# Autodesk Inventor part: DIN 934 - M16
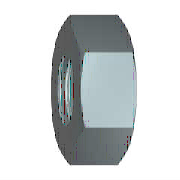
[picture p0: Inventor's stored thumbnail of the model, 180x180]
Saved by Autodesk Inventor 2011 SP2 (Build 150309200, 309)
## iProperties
Created: 2010-02
Part Number: DIN 934 - M16
Material: Stahl, weich, unlegiert
Description: Sechskantmutter
Document SubType Name: Modeling
Standard: DIN 934
Designer: JRE
Standards Organization: DIN
Language: de-DE
Size Designation: M16
Categories: <MemberInstance><Categories><Category DisplayName="Verbindungselemente" InternalName="e4da775c-781d-43d5-af7c-5136215cf5a6" Mnemonic="FSTN"><Category DisplayNam
Density: 1 g/cm^3
IsCustomPart: 0
Author: JRE
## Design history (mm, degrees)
body "Solid1"
workaxis "Work Axis1"
workplane "Work Plane1"
sketch "Skizze1"
  geometry: L1 (-13.856, 0)-(-6.928, 12); L2 (-6.928, 12)-(6.928, 12); L3 (6.928, 12)-(13.856, 0); L4 (13.856, 0)-(6.928, -12); L5 (6.928, -12)-(-6.928, -12); L6 (-6.928, -12)-(-13.856, 0); 2 further points
  constraints: 12 end point, 1 coincident, 1 horizontal, 11 other
  dimensions: "d0" = 27.71281 distance of L3.end L1.start (= 1.1547 x SW)
extrude "Körper" new body sketch "Skizze1" distance "d1" = 13 (= KOH); taper "d2" = 0 deg
revolve "Fase1" stored, may be unused: angle "d7" = 90 deg
sketch "Skizze3"
  geometry: 4 further points
  constraints: 1 coincident, 1 other
hole "Gewinde" sketch "Skizze3" diameter "d25" = 13.835; stored, may be unused: countersink angle "d29" = 82 deg, drill point angle "d31" = 118 deg; dims "d26" = 6, "d27" = 4, "d28" = 2, "d30" = 8
chamfer "Fase2" distance "d8" = 1.08253 (= -0.5 x GD1 + 0.5 x NND); stored, may be unused: angle "d9" = 30 deg, second distance "d40" = 1.08253 (= -0.5 x GD1 + 0.5 x NND)
chamfer "Fase3" distance "d10" = 1.08253 (= -0.5 x GD1 + 0.5 x NND); stored, may be unused: angle "d11" = 30 deg, second distance "d41" = 1.08253 (= -0.5 x GD1 + 0.5 x NND)
sketch "Skizze2"
  geometry: L1 (0, 6.928)-(0, 13.856) reference; L2 (0, 13.856)-(13, 13.856) reference; L3 (13, 6.928)-(13, 13.856) reference; L4 (-2.6, 0)-(15.6, 0) reference; L5 (1.591, 13.856)-(0, 11.1); L6 (11.409, 13.856)-(13, 11.1)
  constraints: 4 end point, 4 point on line
  dimensions: "d3" = 30 deg angle of L1 L5 (= ANG1); "d4" = 30 deg angle of L3 L6 (= ANG2); "d5" = 22.2 diameter of L5.end L4 (= SW0); "d6" = 22.2 diameter of L6.end L4 (= SW01)
other parameters: "ANG1" = 30 deg [user parameter; used in 1 equation term], "ANG2" = 30 deg [user parameter; used in 1 equation term], "NND" = 16 [user parameter; used in 4 equation terms], "KOH" = 13 [user parameter; used in 1 equation term], "SW" = 24 [user parameter; used in 2 equation terms], "SW0" = 22.2 (= SW01) [user parameter; used in 1 equation term], "SW01" = 22.2 [user parameter; used in 2 equation terms], "GD1" = 13.83494 (computed from THREADDIA, PTC, TOA) [user parameter; used in 4 equation terms], "d13" = 0, "d14" = 0, "d39" = 0, "d42" = 0, "GUL" = 1.08253 (= 0.541266 x PTC) [user parameter], "TPU" = 5 (computed from PTC) [user parameter], "THREADDIA" = 16 [user parameter; used in 1 equation term], "TOA" = 30 deg [user parameter; used in 1 equation term], "PTC" = 2 [user parameter; used in 4 equation terms], "E0" = 27.72 (= 1.155 x SW) [user parameter], "GAL" = 1.08253 (= 0.541266 x PTC) [user parameter]
